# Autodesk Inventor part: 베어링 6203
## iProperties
IsCustomPart: 1
Company: 한국ATC센터
Created: 2009-02
Part Number: 베어링 6203
Material: 강, 연강
Description: 깊은 그루브 볼 베어링
Document SubType Name: Modeling
Standard: KS B 2023
Designer: KYOUNG IL JANG
Standards Organization: KS
Language: ko-KR
Size Designation: 6203 - 17 x 40 x 12
Categories: <MemberInstance><Categories><Category DisplayName="샤프트 부품" InternalName="7f7aeb1f-a693-4053-b835-cee3144e0d98" Mnemonic="SHFT"><Category DisplayName="베어링" Inter
Density: 1 g/cm^3
Author: KYOUNG IL JANG
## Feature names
1. IDS_ARRAYBALL[SIMPL:T] [Circular Pattern]
